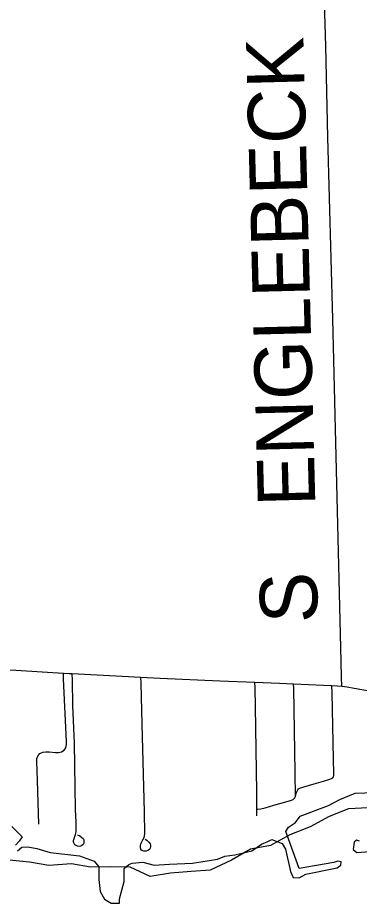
# Model space of a CAD drawing. Extents: x -12 to 34, y 0 to 22.
# Drawn here: x 4.84 to 5.178, y 15.882 to 16.758 of the extents above; entities that cross this region are included whole.
import ezdxf

# ---------------------------------------------------------------- set-up
doc = ezdxf.new("R2010")
doc.units = 0
for name, color, linetype in [('GM_X_Airport_Location_Class_2', 7, 'Continuous'), ('GM_X_Airport_Location_Class_3', 7, 'Continuous'), ('GM_X_County_Road_Text', 7, 'Continuous'), ('GM_X_Major_River', 7, 'Continuous'), ('GM_X_Minor_River', 7, 'Continuous')]:
    doc.layers.add(name, color=color, linetype=linetype)

msp = doc.modelspace()

# ---------------------------------------------------------------- linework, layer by layer
at = {"layer": 'GM_X_Airport_Location_Class_2'}
for points in [[(4.83975, 15.9339), (4.84382, 15.9375), (4.84981, 15.93774), (4.85892, 15.93606), (4.8721, 15.93223), (4.90086, 15.92887), (4.91548, 15.9236), (4.92001, 15.91798), (4.92004, 15.90538), (4.92124, 15.8934), (4.92579, 15.88597), (4.93227, 15.8819), (4.94041, 15.88213), (4.94066, 15.88645), (4.94497, 15.90346), (4.94497, 15.91617), (4.94977, 15.92025), (4.95288, 15.92168), (4.96367, 15.92264), (4.97493, 15.91976), (4.99003, 15.92073), (5.0128, 15.92168), (5.03725, 15.92552), (5.04468, 15.92864), (5.0545, 15.92983), (5.07152, 15.93367), (5.08087, 15.94038), (5.08711, 15.94301), (5.09118, 15.94493), (5.10149, 15.9411), (5.1046, 15.93535), (5.10964, 15.91329), (5.11227, 15.90754), (5.11826, 15.90706), (5.12474, 15.91066), (5.15566, 15.91689), (5.15925, 15.91953), (5.15973, 15.92288), (5.15638, 15.9236), (5.1523, 15.92216), (5.11826, 15.91617), (5.10508, 15.95284), (5.10772, 15.95716), (5.11467, 15.96195), (5.11923, 15.96794), (5.14727, 15.97873), (5.15829, 15.98448), (5.17363, 15.99071), (5.19281, 15.99143)], [(4.83975, 15.9339), (4.84382, 15.9375), (4.84981, 15.93774), (4.85892, 15.93606), (4.8721, 15.93223), (4.90086, 15.92887), (4.91548, 15.9236), (4.92001, 15.91798), (4.92004, 15.90538), (4.92124, 15.8934), (4.92579, 15.88597), (4.93227, 15.8819), (4.94041, 15.88213), (4.94066, 15.88645), (4.94497, 15.90346), (4.94497, 15.91617), (4.94977, 15.92025), (4.95288, 15.92168), (4.96367, 15.92264), (4.97493, 15.91976), (4.99003, 15.92073), (5.0128, 15.92168), (5.03725, 15.92552), (5.04468, 15.92864), (5.0545, 15.92983), (5.07152, 15.93367), (5.08087, 15.94038), (5.08711, 15.94301), (5.09118, 15.94493), (5.10149, 15.9411), (5.1046, 15.93535), (5.10964, 15.91329), (5.11227, 15.90754), (5.11826, 15.90706), (5.12474, 15.91066), (5.15566, 15.91689), (5.15925, 15.91953), (5.15973, 15.92288), (5.15638, 15.9236), (5.1523, 15.92216), (5.11826, 15.91617), (5.10508, 15.95284), (5.10772, 15.95716), (5.11467, 15.96195), (5.11923, 15.96794), (5.14727, 15.97873), (5.15829, 15.98448), (5.17363, 15.99071), (5.19281, 15.99143)], [(4.83399, 15.95788), (4.8443, 15.94757), (4.84142, 15.94349), (4.83759, 15.93942)], [(4.83399, 15.95788), (4.8443, 15.94757), (4.84142, 15.94349), (4.83759, 15.93942)], [(5.17771, 15.94349), (5.17483, 15.94446), (5.17243, 15.94229), (5.17171, 15.9351), (5.17507, 15.93223), (5.18801, 15.93319)], [(5.17771, 15.94349), (5.17483, 15.94446), (5.17243, 15.94229), (5.17171, 15.9351), (5.17507, 15.93223), (5.18801, 15.93319)]]:
    msp.add_lwpolyline(points, dxfattribs=at)
at = {"layer": 'GM_X_Airport_Location_Class_3'}
msp.add_line((4.89378, 16.10922), (4.96175, 16.10568), dxfattribs=at)
for points in [[(4.76951, 16.11624), (4.78558, 16.11538), (4.83803, 16.11241), (4.88498, 16.10971)], [(4.88498, 16.10971), (4.89078, 16.10938), (4.89378, 16.10922)], [(4.96175, 16.10568), (4.98081, 16.10469), (5.03984, 16.10209), (5.07446, 16.10073)], [(5.07446, 16.10073), (5.09885, 16.09978), (5.11267, 16.09914)], [(5.11267, 16.09914), (5.14231, 16.09777), (5.15051, 16.09735)], [(5.15051, 16.09735), (5.15558, 16.09708), (5.16019, 16.09675)], [(5.16019, 16.09675), (5.16558, 16.09601), (5.17242, 16.09476), (5.18227, 16.09305), (5.23096, 16.08296), (5.27675, 16.07346)]]:
    msp.add_lwpolyline(points, dxfattribs=at)
at = {"layer": 'GM_X_Major_River'}
msp.add_line((5.07626, 15.96833), (5.07628, 15.97482), dxfattribs=at)
for points in [[(5.16019, 16.09675), (5.16, 16.10562), (5.15978, 16.12118), (5.15135, 16.45977), (5.14666, 16.63993), (5.14438, 16.73001), (5.14189, 16.81697), (5.13791, 16.93805), (5.13395, 17.07161), (5.13123, 17.16168), (5.12865, 17.24551), (5.12595, 17.35732), (5.12591, 17.35933)], [(4.86069, 15.96016), (4.85947, 16.00351), (4.85861, 16.02215), (4.85892, 16.02525), (4.85999, 16.02802), (4.8619, 16.03021), (4.86469, 16.03141), (4.86782, 16.0318), (4.87093, 16.03175), (4.87709, 16.03118), (4.8803, 16.03116), (4.88332, 16.0318), (4.88579, 16.03336), (4.88732, 16.03586), (4.88802, 16.03884), (4.88803, 16.04208), (4.88524, 16.10401), (4.88498, 16.10971)], [(4.89888, 15.94955), (4.90115, 15.94864), (4.90341, 15.9471), (4.90446, 15.94585), (4.90509, 15.94455), (4.90528, 15.94296), (4.90515, 15.94144), (4.90451, 15.94012), (4.90342, 15.93913), (4.9023, 15.93853), (4.90081, 15.9382), (4.89913, 15.93834), (4.89763, 15.93897), (4.89648, 15.93983), (4.89566, 15.94089), (4.89518, 15.94228), (4.89508, 15.94417), (4.89556, 15.94604), (4.89633, 15.94806), (4.89701, 15.94989), (4.89759, 15.95244), (4.89768, 15.95602), (4.89754, 15.96227), (4.89703, 15.97469), (4.89586, 16.04022), (4.8945, 16.07769), (4.89393, 16.10266), (4.89378, 16.10922)], [(4.96593, 15.94545), (4.96747, 15.94425), (4.96968, 15.9424), (4.97078, 15.94081), (4.97118, 15.93935), (4.97127, 15.93776), (4.97096, 15.93644), (4.97021, 15.9352), (4.96866, 15.93396), (4.96684, 15.93349), (4.96465, 15.93344), (4.96346, 15.93379), (4.96235, 15.93454), (4.96169, 15.9356), (4.96125, 15.93723), (4.96126, 15.93892), (4.96156, 15.94037), (4.96212, 15.9419), (4.96367, 15.94452), (4.96482, 15.94704), (4.96531, 15.9488), (4.96548, 15.95049), (4.96512, 15.97226), (4.96298, 16.05923), (4.96191, 16.09961), (4.96175, 16.10568)], [(5.07628, 15.97482), (5.0763, 15.98174), (5.07628, 15.99233), (5.07507, 16.07639), (5.07461, 16.09507), (5.07446, 16.10073)], [(5.11439, 15.98751), (5.11405, 16.0114), (5.11275, 16.09454), (5.11267, 16.09914)], [(5.15208, 16.0069), (5.15248, 16.00832), (5.15259, 16.01048), (5.15216, 16.02463), (5.15068, 16.09011), (5.15051, 16.09735)], [(5.11439, 15.98751), (5.11514, 15.99009), (5.11553, 15.99138), (5.11603, 15.99284), (5.11674, 15.99412), (5.11766, 15.99505), (5.11897, 15.99591), (5.12189, 15.99694), (5.13064, 15.99954), (5.14237, 16.00274), (5.14844, 16.00459), (5.1502, 16.0053), (5.15137, 16.00606), (5.15208, 16.0069)], [(5.07628, 15.97482), (5.07715, 15.97496), (5.08026, 15.97543), (5.0844, 15.97633), (5.09327, 15.97886), (5.10514, 15.98218), (5.11057, 15.98384), (5.1121, 15.98466), (5.11309, 15.98547), (5.11383, 15.98639), (5.11439, 15.98751)]]:
    msp.add_lwpolyline(points, dxfattribs=at)
at = {"layer": 'GM_X_Minor_River'}
msp.add_lwpolyline([(5.18626, 15.97626), (5.16691, 15.9755), (5.14793, 15.9679), (5.12896, 15.95764), (5.10885, 15.94966), (5.08987, 15.93902), (5.07014, 15.9356), (5.05116, 15.92459), (5.0303, 15.91471), (5.01132, 15.91319), (4.99083, 15.91167), (4.97071, 15.90825), (4.95098, 15.91774), (4.93162, 15.91812), (4.91189, 15.91773), (4.89291, 15.92077), (4.87052, 15.91925), (4.85155, 15.92267), (4.83182, 15.92456), (4.8117, 15.9314)], dxfattribs=at)

# ---------------------------------------------------------------- texts
at = {"layer": 'GM_X_County_Road_Text'}
for s, height, rotation, p in [('ENGLEBECK', 0.056818, 91.47474, (5.13424, 16.27518)), ('S', 0.05682, 91.2447, (5.13674, 16.15951))]:
    msp.add_text(s, height=height, rotation=rotation, dxfattribs=at).set_placement(p)

doc.saveas('drawing.dxf')
